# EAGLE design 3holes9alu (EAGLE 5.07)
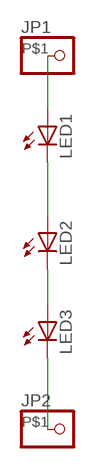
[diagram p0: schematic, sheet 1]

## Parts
JP1  PINHD-1X1SMD50  [1SMD]
JP2  PINHD-1X1SMD50  [1SMD]
LED1  LED1W_HOLE  [1W]
LED2  LED1W_HOLE  [1W]
LED3  LED1W_HOLE  [1W]

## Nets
N$1: LED1.C LED2.A
N$2: LED2.C LED3.A
N$3: JP1.P$1 LED1.A
N$4: JP2.P$1 LED3.C

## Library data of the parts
JP1 JP2 = pinhead:PINHD-1X1: PIN HEADER
LED1-LED3 = led:LED: LED

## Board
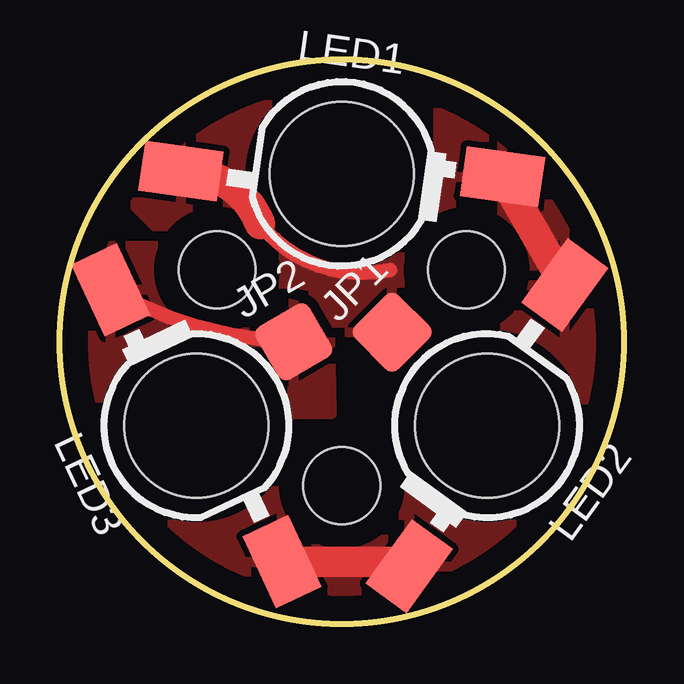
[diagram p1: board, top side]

Size 23.5 x 23.5 mm. Coordinates in mm from the lower left corner, seen from the top.
Outline: circle at 11.75,11.75 radius 11.75
Copper layers (1*16): Top 0.035mm / dielectric 1.5mm / Bottom 0.035mm
Design rules "default": minimum track width 10mil, minimum drill 24mil, track to track 8mil, track to pad 8mil, pad to pad 8mil, via to via 8mil, smd to smd 8mil, copper to edge 40mil, drill to drill 8mil, minimum pad ring 10mil, minimum via ring 8mil, stop-mask expansion 4mil, vias tented up to drill 0mil, thermal gap 10mil
Holes 3.2 mm at 16.95,14.75 11.75,5.75 6.55,14.75

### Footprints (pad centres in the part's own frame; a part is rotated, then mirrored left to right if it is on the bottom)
1SMD = smd 2.54 x 2.54: P$1 0,0
1W = smd 3.3 x 2.1: A -6.65,-0.82; C 6.65,0.82 | hole 6: 0,0

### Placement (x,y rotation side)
JP1  13.85,12.15 45 top
JP2  9.75,11.75 30 top
LED1  11.75,18.75 352 top
LED2  17.81,8.25 234 top
LED3  5.69,8.25 115.2 top

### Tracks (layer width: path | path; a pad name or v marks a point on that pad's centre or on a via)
N$1
  Top 1.27: LED2.A LED1.C
  pour Top: 15.75,22.75 15.75,8.75 22.75,8.75 23.75,9.75 arc35 17.75,22.75
N$2
  Top 1.27: LED3.A 14.49,2.58 arc-90 LED2.C
  pour Top (rank 2): 2.75,7.75 20.75,7.75 20.75,4.75 arc-96 2.75,4.75
N$3
  Top 0.61: 8.35,16.65 arc64 13.75,14.75
  Top 1.27: LED1.A arc-70 8.35,16.65
  pour Top (isolate 0.406, rank 2): 4.75,20.75 5.75,21.75 arc-51 14.75,22.75 14.75,11.75 13.75,10.75 9.75,10.75 2.75,17.75
N$4
  Top 0.61: LED3.C arc28 JP2.P$1
  pour Top: 0.75,15.75 0.75,8.75 11.35,8.75 11.25,12.95 7.75,13.75 5.75,15.75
